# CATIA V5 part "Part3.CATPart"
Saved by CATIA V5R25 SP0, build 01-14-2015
Part number: Part3
Bounding box of the stored display mesh (mm): x -5.5 to 5.5, y 0 to 75, z -5.5 to 5.5
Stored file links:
  D:\kin uygulama8\Part3.CATPart
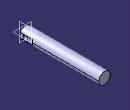
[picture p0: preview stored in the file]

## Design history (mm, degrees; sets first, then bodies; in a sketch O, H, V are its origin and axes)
Body1 (main body)
  Sketch1 on zx-plane, origin (0, 0, 0), H (-1, 0, 0), V (0, 0, 1)
    circle A1 centre (0, 0) radius 5.5
    radius A1 = 5.5
  Pad1: profile Sketch1, direction (0, 1, 0), length 75
  Sketch2 on start face of Pad1, origin (0, 0, 0), H (1, 0, 0), V (0, 0, 1)
    line L1 (5, 4.9783) -> (5, -5.2804)
    distance V L1 = 5
    vertical: L1 V
  Pocket1: profile Sketch2, direction (0, 1, 0), length 12
  Mirror1: of Pocket1, about yz-plane
  Sketch3 on face of Pocket1 from Sketch2.L1, origin (5, 0, 0), H (0, 1, 0), V (0, 0, 1)
    circle A1 centre (5, 0) radius 2.5
    point P1 (5, 0)
    radius A1 = 2.5
    distance P1 V = 5
    coincidence: P1 H
  Pocket2: profile Sketch3, direction (-1, 0, 0), through (limit type 6)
